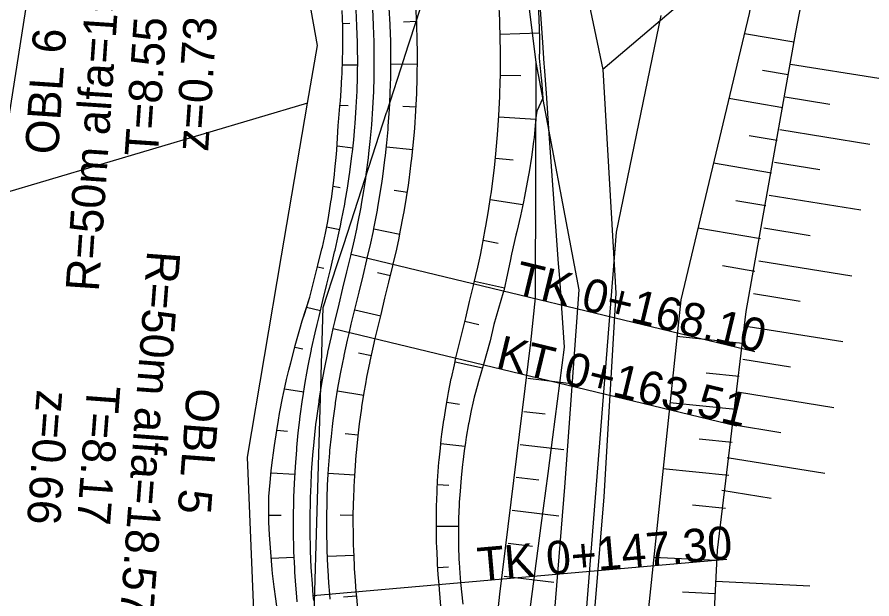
# Model space of a CAD drawing. Extents: x -583721 to -583071, y -1166145 to -1165065.
# Drawn here: x -583433.1 to -583381.7, y -1165506 to -1165470.9 of the extents above; entities that cross this region are included whole.
import ezdxf

# ---------------------------------------------------------------- set-up
doc = ezdxf.new("R2010")
doc.units = 0
for name, color, linetype in [('01_DOPRAVA', 7, 'Continuous'), ('03_PC_POPIS_NAVRH', 7, 'Continuous'), ('13', 7, 'Continuous'), ('14', 7, 'Continuous'), ('21', 7, 'Continuous'), ('_Rozpiska', 7, 'Continuous'), ('Kabel_navrh', 7, 'Continuous'), ('KOTY', 7, 'Continuous'), ('North Arrow', 7, 'Continuous'), ('Popis PP', 7, 'Continuous'), ('Rámy', 7, 'Continuous'), ('TISK', 7, 'Continuous')]:
    doc.layers.add(name, color=color, linetype=linetype)

msp = doc.modelspace()

# ---------------------------------------------------------------- linework, layer by layer
at = {"layer": '01_DOPRAVA'}
msp.add_line((-583415.62, -1165476.12), (-583516.013, -1165505.958), dxfattribs=at)
for points in [[(-583415.62, -1165476.12), (-583415.02, -1165472.65), (-583420.22, -1165443.6), (-583448.97, -1165365.39), (-583458.92, -1165347.2), (-583477.78, -1165313.78)], [(-583394.35, -1165470.85), (-583397.05, -1165483.9), (-583399.8, -1165518.65), (-583400, -1165542.33), (-583402.51, -1165559.81), (-583402.19, -1165563.54), (-583409.42, -1165564.02), (-583405.3, -1165586.77), (-583405.42, -1165638.41)], [(-583421.75, -1165552.72), (-583418.41, -1165517.42), (-583419.25, -1165497.44), (-583417.19, -1165485.32), (-583415.62, -1165476.12)]]:
    msp.add_lwpolyline(points, dxfattribs=at)
at = {"layer": '03_PC_POPIS_NAVRH'}
for points in [[(-583461.59, -1165302.25), (-583452.7, -1165330.11), (-583439.53, -1165361.89), (-583424.49, -1165398.09), (-583411.01, -1165432.01), (-583399.44, -1165466.53), (-583397.85, -1165474.11)], [(-583464.75, -1165303.13), (-583454.71, -1165331.15), (-583441.76, -1165362.61), (-583427, -1165399.08), (-583414.01, -1165432.94), (-583402.68, -1165467.21), (-583401.88, -1165473.68), (-583399.3, -1165487.37), (-583400.15, -1165499.25), (-583403.33, -1165538.26), (-583407.25, -1165561.02), (-583404.58, -1165574.64), (-583401.09, -1165602.76), (-583401.09, -1165613.37), (-583400.94, -1165621.86)], [(-583397.85, -1165474.11), (-583397.06, -1165487.57), (-583397.79, -1165499.84), (-583401.04, -1165539.21), (-583404.66, -1165561.5), (-583402.08, -1165573.97), (-583398.96, -1165602.08), (-583398.51, -1165613.27), (-583398.57, -1165622.21), (-583397.66, -1165628.38), (-583396.16, -1165631.68), (-583394.63, -1165634.22), (-583391.58, -1165635.84)]]:
    msp.add_lwpolyline(points, dxfattribs=at)
at = {"layer": '13'}
msp.add_lwpolyline([(-583416.289, -1165543.841), (-583416.022, -1165534.608), (-583415.796, -1165526.827), (-583415.773, -1165526.042), (-583415.472, -1165515.657), (-583415.378, -1165512.4), (-583415.341, -1165511.129), (-583415.238, -1165507.583), (-583415.019, -1165500.002), (-583414.683, -1165488.44), (-583413.859, -1165485.904), (-583413.741, -1165485.542), (-583413.723, -1165485.486), (-583413.45, -1165484.646), (-583410.865, -1165476.699), (-583410.858, -1165476.678), (-583409.783, -1165473.372), (-583409.781, -1165473.366), (-583407.515, -1165466.397)], dxfattribs=at)
at = {"layer": '14'}
for p, q in [((-583413.087, -1165471.34), (-583413.515, -1165471.359)), ((-583409.859, -1165471.234), (-583409.06, -1165471.199)), ((-583404.031, -1165471.963), (-583401.672, -1165471.901)), ((-583413.528, -1165473.815), (-583412.612, -1165473.82)), ((-583410.611, -1165473.768), (-583409.011, -1165473.776)), ((-583402.794, -1165474.483), (-583404.017, -1165474.463)), ((-583413.182, -1165476.291), (-583413.674, -1165476.262)), ((-583409.884, -1165476.31), (-583409.086, -1165476.353)), ((-583404.113, -1165476.961), (-583401.887, -1165477.095)), ((-583413.847, -1165478.706), (-583412.897, -1165478.81)), ((-583410.881, -1165478.759), (-583409.289, -1165478.924)), ((-583403.257, -1165479.563), (-583404.317, -1165479.452)), ((-583413.661, -1165481.218), (-583414.092, -1165481.149)), ((-583410.408, -1165481.359), (-583409.618, -1165481.481)), ((-583404.629, -1165481.933), (-583402.658, -1165482.225)), ((-583414.477, -1165483.579), (-583413.691, -1165483.744)), ((-583411.638, -1165483.699), (-583410.069, -1165484.017)), ((-583404.144, -1165484.571), (-583405.05, -1165484.397)), ((-583414.644, -1165486.087), (-583415.029, -1165485.996)), ((-583411.413, -1165486.319), (-583410.634, -1165486.502)), ((-583405.574, -1165486.841), (-583403.772, -1165487.251)), ((-583415.68, -1165488.413), (-583414.845, -1165488.609)), ((-583412.778, -1165488.567), (-583411.222, -1165488.938)), ((-583405.307, -1165489.477), (-583406.159, -1165489.272)), ((-583415.903, -1165490.943), (-583416.4, -1165490.841)), ((-583412.568, -1165491.167), (-583411.785, -1165491.334)), ((-583406.744, -1165491.702), (-583405.1, -1165492.068)), ((-583417.005, -1165493.324), (-583415.852, -1165493.505)), ((-583413.82, -1165493.456), (-583412.241, -1165493.716)), ((-583406.486, -1165494.283), (-583407.244, -1165494.151)), ((-583416.831, -1165495.913), (-583417.482, -1165495.843)), ((-583413.368, -1165496.022), (-583412.573, -1165496.111)), ((-583407.599, -1165496.626), (-583406.156, -1165496.789)), ((-583417.82, -1165498.392), (-583416.386, -1165498.474)), ((-583414.38, -1165498.422), (-583412.783, -1165498.52)), ((-583407.116, -1165499.154), (-583407.808, -1165499.116)), ((-583417.217, -1165500.966), (-583417.965, -1165500.96)), ((-583413.667, -1165500.928), (-583412.867, -1165500.936)), ((-583407.87, -1165501.615), (-583406.537, -1165501.609)), ((-583414.428, -1165503.42), (-583412.829, -1165503.355)), ((-583417.813, -1165503.527), (-583416.427, -1165503.472)), ((-583407.135, -1165504.076), (-583407.784, -1165504.113)), ((-583413.467, -1165505.853), (-583412.669, -1165505.792))]:
    msp.add_line(p, q, dxfattribs=at)
at = {"layer": '21'}
for points in [[(-583401.753, -1165469.827), (-583401.694, -1165471.025), (-583401.693, -1165471.072), (-583401.664, -1165472.224), (-583401.66, -1165472.918), (-583401.673, -1165473.423), (-583401.559, -1165474.624), (-583401.546, -1165474.767), (-583401.463, -1165475.83), (-583401.823, -1165476.606), (-583401.879, -1165477.011), (-583401.99, -1165478.203), (-583402.02, -1165478.439), (-583402.152, -1165479.388), (-583402.289, -1165480.262), (-583402.342, -1165480.569), (-583402.559, -1165481.744), (-583402.625, -1165482.071), (-583402.804, -1165482.912), (-583403.025, -1165483.864), (-583403.077, -1165484.073), (-583403.354, -1165485.231), (-583403.434, -1165485.65), (-583403.585, -1165486.397), (-583403.814, -1165487.441), (-583403.84, -1165487.538), (-583404.402, -1165489.46), (-583404.633, -1165490.433), (-583405.041, -1165491.872), (-583405.161, -1165492.267), (-583405.377, -1165493.027), (-583405.384, -1165493.052), (-583405.591, -1165493.843), (-583405.677, -1165494.193), (-583405.781, -1165494.639), (-583405.925, -1165495.373), (-583405.938, -1165495.442), (-583406.075, -1165496.25), (-583406.123, -1165496.562), (-583406.195, -1165497.06), (-583406.284, -1165497.759), (-583406.297, -1165497.873), (-583406.382, -1165498.689), (-583406.406, -1165498.961), (-583406.448, -1165499.507), (-583406.489, -1165500.166), (-583406.497, -1165500.326), (-583406.529, -1165501.147), (-583406.534, -1165501.375), (-583406.542, -1165501.968), (-583406.541, -1165502.585), (-583406.538, -1165502.79), (-583406.511, -1165503.611), (-583406.502, -1165503.795), (-583406.463, -1165504.432), (-583406.42, -1165505.003), (-583406.285, -1165506.299)], [(-583414.257, -1165505.995), (-583414.284, -1165505.693), (-583414.339, -1165505.012), (-583414.389, -1165504.253), (-583414.401, -1165504.034), (-583414.444, -1165503.055), (-583414.451, -1165502.811), (-583414.467, -1165502.075), (-583414.471, -1165501.368), (-583414.47, -1165501.095), (-583414.454, -1165500.115), (-583414.449, -1165499.925), (-583414.418, -1165499.136), (-583414.383, -1165498.483), (-583414.363, -1165498.158), (-583414.288, -1165497.18), (-583414.276, -1165497.043), (-583414.194, -1165496.205), (-583414.126, -1165495.607), (-583414.08, -1165495.232), (-583413.946, -1165494.261), (-583413.934, -1165494.177), (-583413.794, -1165493.293), (-583413.7, -1165492.753), (-583413.622, -1165492.328), (-583413.43, -1165491.367), (-583413.424, -1165491.336), (-583413.22, -1165490.41), (-583413.106, -1165489.928), (-583412.99, -1165489.447), (-583412.756, -1165488.475), (-583412.521, -1165487.503), (-583412.287, -1165486.53), (-583412.053, -1165485.558), (-583412.029, -1165485.46), (-583411.822, -1165484.567), (-583411.684, -1165483.928), (-583411.611, -1165483.569), (-583411.42, -1165482.567), (-583411.387, -1165482.385), (-583411.248, -1165481.562), (-583411.137, -1165480.835), (-583411.097, -1165480.553), (-583410.967, -1165479.541), (-583410.936, -1165479.277), (-583410.856, -1165478.527), (-583410.782, -1165477.714), (-583410.766, -1165477.511), (-583410.696, -1165476.494), (-583410.677, -1165476.147), (-583410.646, -1165475.475), (-583410.619, -1165474.577), (-583410.617, -1165474.455), (-583410.608, -1165473.435), (-583410.611, -1165473.006), (-583410.62, -1165472.416), (-583410.65, -1165471.436), (-583410.652, -1165471.396), (-583410.704, -1165470.377)], [(-583412.576, -1165506.851), (-583412.664, -1165505.855), (-583412.69, -1165505.553), (-583412.743, -1165504.894), (-583412.791, -1165504.161), (-583412.803, -1165503.948), (-583412.845, -1165503.001), (-583412.852, -1165502.766), (-583412.867, -1165502.054), (-583412.871, -1165501.369), (-583412.87, -1165501.106), (-583412.855, -1165500.158), (-583412.849, -1165499.973), (-583412.82, -1165499.21), (-583412.786, -1165498.578), (-583412.766, -1165498.264), (-583412.694, -1165497.319), (-583412.682, -1165497.186), (-583412.603, -1165496.375), (-583412.537, -1165495.797), (-583412.493, -1165495.434), (-583412.364, -1165494.494), (-583412.351, -1165494.413), (-583412.216, -1165493.558), (-583412.125, -1165493.035), (-583412.049, -1165492.625), (-583411.864, -1165491.695), (-583411.858, -1165491.665), (-583411.661, -1165490.769), (-583411.551, -1165490.303), (-583411.435, -1165489.822), (-583411.2, -1165488.85), (-583410.966, -1165487.878), (-583410.732, -1165486.906), (-583410.497, -1165485.933), (-583410.474, -1165485.835), (-583410.26, -1165484.914), (-583410.118, -1165484.255), (-583410.042, -1165483.885), (-583409.845, -1165482.851), (-583409.812, -1165482.664), (-583409.668, -1165481.814), (-583409.554, -1165481.065), (-583409.513, -1165480.774), (-583409.378, -1165479.731), (-583409.346, -1165479.458), (-583409.264, -1165478.685), (-583409.188, -1165477.846), (-583409.171, -1165477.637), (-583409.099, -1165476.587), (-583409.079, -1165476.229), (-583409.047, -1165475.537), (-583409.02, -1165474.61), (-583409.017, -1165474.485), (-583409.008, -1165473.433), (-583409.011, -1165472.991), (-583409.02, -1165472.381), (-583409.052, -1165471.371), (-583409.053, -1165471.33), (-583409.107, -1165470.279)], [(-583407.595, -1165506.414), (-583407.683, -1165505.418), (-583407.709, -1165505.116), (-583407.757, -1165504.527), (-583407.8, -1165503.871), (-583407.81, -1165503.681), (-583407.847, -1165502.834), (-583407.854, -1165502.623), (-583407.867, -1165501.986), (-583407.871, -1165501.374), (-583407.87, -1165501.138), (-583407.856, -1165500.29), (-583407.852, -1165500.125), (-583407.825, -1165499.443), (-583407.795, -1165498.877), (-583407.777, -1165498.596), (-583407.713, -1165497.751), (-583407.702, -1165497.632), (-583407.631, -1165496.907), (-583407.573, -1165496.389), (-583407.532, -1165496.064), (-583407.417, -1165495.224), (-583407.406, -1165495.152), (-583407.285, -1165494.387), (-583407.204, -1165493.919), (-583407.136, -1165493.552), (-583406.971, -1165492.72), (-583406.965, -1165492.693), (-583406.788, -1165491.892), (-583406.69, -1165491.475), (-583406.574, -1165490.994), (-583406.34, -1165490.022), (-583406.105, -1165489.05), (-583405.871, -1165488.077), (-583405.637, -1165487.105), (-583405.613, -1165487.007), (-583405.379, -1165485.998), (-583405.224, -1165485.276), (-583405.141, -1165484.871), (-583404.925, -1165483.74), (-583404.888, -1165483.535), (-583404.731, -1165482.604), (-583404.606, -1165481.783), (-583404.561, -1165481.465), (-583404.413, -1165480.322), (-583404.378, -1165480.024), (-583404.288, -1165479.177), (-583404.205, -1165478.258), (-583404.186, -1165478.03), (-583404.107, -1165476.88), (-583404.085, -1165476.488), (-583404.051, -1165475.73), (-583404.021, -1165474.715), (-583404.018, -1165474.578), (-583404.008, -1165473.426), (-583404.011, -1165472.941), (-583404.021, -1165472.274), (-583404.056, -1165471.168), (-583404.058, -1165471.123), (-583404.117, -1165469.973)], [(-583417.499, -1165506.279), (-583417.539, -1165505.978), (-583417.634, -1165505.255), (-583417.727, -1165504.447), (-583417.751, -1165504.213), (-583417.845, -1165503.169), (-583417.865, -1165502.909), (-583417.917, -1165502.122), (-583417.954, -1165501.365), (-583417.965, -1165501.073), (-583417.964, -1165500.022), (-583417.949, -1165499.818), (-583417.878, -1165498.975), (-583417.808, -1165498.277), (-583417.769, -1165497.931), (-583417.638, -1165496.89), (-583417.617, -1165496.744), (-583417.483, -1165495.853), (-583417.377, -1165495.22), (-583417.306, -1165494.821), (-583417.107, -1165493.795), (-583417.088, -1165493.706), (-583416.884, -1165492.773), (-583416.75, -1165492.205), (-583416.64, -1165491.759), (-583416.376, -1165490.75), (-583416.368, -1165490.717), (-583416.092, -1165489.748), (-583415.94, -1165489.244), (-583415.792, -1165488.771), (-583415.493, -1165487.815), (-583415.246, -1165486.846), (-583414.998, -1165485.877), (-583414.758, -1165484.906), (-583414.734, -1165484.808), (-583414.549, -1165483.961), (-583414.434, -1165483.354), (-583414.373, -1165483.013), (-583414.219, -1165482.062), (-583414.194, -1165481.889), (-583414.086, -1165481.108), (-583414.003, -1165480.419), (-583413.974, -1165480.151), (-583413.884, -1165479.194), (-583413.864, -1165478.944), (-583413.814, -1165478.235), (-583413.774, -1165477.466), (-583413.766, -1165477.275), (-583413.679, -1165476.319), (-583413.651, -1165475.992), (-583413.603, -1165475.361), (-583413.554, -1165474.515), (-583413.549, -1165474.401), (-583413.515, -1165473.439), (-583413.507, -1165473.035), (-583413.502, -1165472.477), (-583413.509, -1165471.552), (-583413.51, -1165471.514), (-583413.539, -1165470.552)], [(-583417.1, -1165509.255), (-583417.539, -1165505.978), (-583417.634, -1165505.255), (-583417.727, -1165504.447), (-583417.751, -1165504.213), (-583417.845, -1165503.169), (-583417.865, -1165502.909), (-583417.917, -1165502.122), (-583417.954, -1165501.365), (-583417.965, -1165501.073), (-583417.964, -1165500.022), (-583417.949, -1165499.818), (-583417.878, -1165498.975), (-583417.808, -1165498.277), (-583417.769, -1165497.931), (-583417.638, -1165496.89), (-583417.617, -1165496.744), (-583417.483, -1165495.853), (-583417.377, -1165495.22), (-583417.306, -1165494.821), (-583417.107, -1165493.795), (-583417.088, -1165493.706), (-583416.884, -1165492.773), (-583416.75, -1165492.205), (-583416.64, -1165491.759), (-583416.376, -1165490.75), (-583416.368, -1165490.717), (-583416.092, -1165489.748), (-583415.94, -1165489.244), (-583415.493, -1165487.815), (-583414.998, -1165485.877), (-583414.758, -1165484.906), (-583414.734, -1165484.808), (-583414.549, -1165483.961), (-583414.434, -1165483.354), (-583414.373, -1165483.013), (-583414.219, -1165482.062), (-583414.194, -1165481.889), (-583414.086, -1165481.108), (-583414.003, -1165480.419), (-583413.974, -1165480.151), (-583413.884, -1165479.194), (-583413.864, -1165478.944), (-583413.814, -1165478.235), (-583413.774, -1165477.466), (-583413.766, -1165477.275), (-583413.679, -1165476.319), (-583413.651, -1165475.992), (-583413.603, -1165475.361), (-583413.554, -1165474.515), (-583413.549, -1165474.401), (-583413.515, -1165473.439), (-583413.507, -1165473.035), (-583413.502, -1165472.477), (-583413.509, -1165471.552), (-583413.51, -1165471.514), (-583413.539, -1165470.552)], [(-583416.25, -1165506.169), (-583416.276, -1165505.868), (-583416.333, -1165505.159), (-583416.385, -1165504.369), (-583416.398, -1165504.141), (-583416.443, -1165503.122), (-583416.45, -1165502.868), (-583416.467, -1165502.102), (-583416.471, -1165501.366), (-583416.47, -1165501.082), (-583416.453, -1165500.062), (-583416.448, -1165499.864), (-583416.416, -1165499.043), (-583416.38, -1165498.363), (-583416.358, -1165498.025), (-583416.281, -1165497.008), (-583416.268, -1165496.865), (-583416.182, -1165495.992), (-583416.112, -1165495.371), (-583416.064, -1165494.979), (-583415.925, -1165493.969), (-583415.912, -1165493.882), (-583415.766, -1165492.961), (-583415.668, -1165492.399), (-583415.587, -1165491.957), (-583415.388, -1165490.957), (-583415.381, -1165490.924), (-583415.169, -1165489.961), (-583415.05, -1165489.459), (-583414.935, -1165488.978), (-583414.7, -1165488.006), (-583414.466, -1165487.034), (-583414.231, -1165486.062), (-583413.997, -1165485.09), (-583413.973, -1165484.991), (-583413.774, -1165484.133), (-583413.642, -1165483.519), (-583413.572, -1165483.174), (-583413.388, -1165482.212), (-583413.357, -1165482.037), (-583413.223, -1165481.246), (-583413.117, -1165480.547), (-583413.078, -1165480.276), (-583412.953, -1165479.305), (-583412.923, -1165479.051), (-583412.846, -1165478.33), (-583412.775, -1165477.549), (-583412.76, -1165477.354), (-583412.692, -1165476.377), (-583412.674, -1165476.043), (-583412.645, -1165475.398), (-583412.619, -1165474.535), (-583412.617, -1165474.418), (-583412.608, -1165473.438), (-583412.611, -1165473.026), (-583412.619, -1165472.458), (-583412.649, -1165471.517), (-583412.65, -1165471.479), (-583412.701, -1165470.5)]]:
    msp.add_lwpolyline(points, dxfattribs=at)
at = {"layer": '_Rozpiska'}
for points in [[(-583386.35, -1165472.46), (-583389.33, -1165471.95)], [(-583386.56, -1165473.77), (-583381.24, -1165474.63)], [(-583386.69, -1165474.43), (-583388.24, -1165474.17)], [(-583387.02, -1165476.4), (-583390.26, -1165475.85)], [(-583386.88, -1165475.75), (-583384.19, -1165476.18)], [(-583387.36, -1165478.37), (-583389.04, -1165478.09)], [(-583387.19, -1165477.72), (-583381.78, -1165478.59)], [(-583387.51, -1165479.69), (-583384.78, -1165480.13)], [(-583387.69, -1165480.35), (-583391.19, -1165479.75)], [(-583387.83, -1165481.67), (-583382.32, -1165482.56)], [(-583388.03, -1165482.32), (-583389.84, -1165482.01)], [(-583388.36, -1165484.29), (-583392.13, -1165483.65)], [(-583388.15, -1165483.64), (-583385.37, -1165484.09)], [(-583388.46, -1165485.62), (-583382.86, -1165486.52)], [(-583388.7, -1165486.26), (-583390.65, -1165485.93)], [(-583388.78, -1165487.59), (-583385.96, -1165488.05)], [(-583389.1, -1165489.57), (-583383.4, -1165490.48)], [(-583389.44, -1165490.6), (-583393.39, -1165490.19)], [(-583402.13, -1165490.72), (-583400.94, -1165490.86)], [(-583389.42, -1165491.54), (-583386.55, -1165492)], [(-583389.65, -1165492.59), (-583391.62, -1165492.39)], [(-583402.36, -1165492.7), (-583399.91, -1165493)], [(-583389.74, -1165493.52), (-583383.94, -1165494.45)], [(-583389.85, -1165494.58), (-583393.81, -1165494.17)], [(-583402.6, -1165494.69), (-583401.32, -1165494.84)], [(-583390.05, -1165495.49), (-583387.13, -1165495.96)], [(-583402.83, -1165496.68), (-583400.2, -1165496.99)], [(-583390.06, -1165496.57), (-583392.04, -1165496.37)], [(-583390.37, -1165497.47), (-583384.49, -1165498.41)], [(-583390.26, -1165498.56), (-583394.23, -1165498.15)], [(-583403.07, -1165498.66), (-583401.71, -1165498.82)], [(-583390.69, -1165499.44), (-583387.72, -1165499.92)], [(-583403.31, -1165500.65), (-583400.49, -1165500.98)], [(-583390.47, -1165500.55), (-583392.45, -1165500.34)], [(-583403.54, -1165502.63), (-583402.09, -1165502.81)], [(-583391, -1165503.68), (-583394.79, -1165503.49)], [(-583403.78, -1165504.62), (-583400.79, -1165504.98)], [(-583391.04, -1165504.91), (-583385.38, -1165505.2)], [(-583391.1, -1165505.68), (-583393.05, -1165505.58)]]:
    msp.add_lwpolyline(points, dxfattribs=at)
at = {"layer": 'Kabel_navrh'}
for points in [[(-583385.69, -1165452.31), (-583390.55, -1165467.88), (-583397.85, -1165474.11)], [(-583401.88, -1165473.68), (-583401.92, -1165487.86), (-583402.21, -1165490.54), (-583404.08, -1165505.7), (-583406.44, -1165527.95), (-583408.58, -1165548.59), (-583408.74, -1165560.73), (-583406.71, -1165575), (-583403.13, -1165607.61), (-583402.39, -1165613.68), (-583402.34, -1165622.12), (-583399.97, -1165635.46)]]:
    msp.add_lwpolyline(points, dxfattribs=at)
at = {"layer": 'KOTY'}
msp.add_lwpolyline([(-583415.254, -1165506.082), (-583415.28, -1165505.78), (-583415.336, -1165505.085), (-583415.387, -1165504.311), (-583415.4, -1165504.087), (-583415.443, -1165503.088), (-583415.451, -1165502.84), (-583415.467, -1165502.089), (-583415.471, -1165501.367), (-583415.47, -1165501.089), (-583415.454, -1165500.089), (-583415.448, -1165499.894), (-583415.417, -1165499.09), (-583415.382, -1165498.423), (-583415.361, -1165498.091), (-583415.284, -1165497.094), (-583415.272, -1165496.954), (-583415.188, -1165496.099), (-583415.119, -1165495.489), (-583415.072, -1165495.106), (-583414.936, -1165494.115), (-583414.923, -1165494.029), (-583414.78, -1165493.127), (-583414.684, -1165492.576), (-583414.604, -1165492.143), (-583414.409, -1165491.162), (-583414.402, -1165491.13), (-583414.194, -1165490.185), (-583414.078, -1165489.693), (-583413.962, -1165489.213), (-583413.728, -1165488.24), (-583413.494, -1165487.268), (-583413.259, -1165486.296), (-583413.025, -1165485.324), (-583413.001, -1165485.226), (-583412.798, -1165484.35), (-583412.663, -1165483.723), (-583412.591, -1165483.372), (-583412.404, -1165482.389), (-583412.372, -1165482.211), (-583412.236, -1165481.404), (-583412.127, -1165480.691), (-583412.088, -1165480.415), (-583411.96, -1165479.423), (-583411.929, -1165479.164), (-583411.851, -1165478.429), (-583411.779, -1165477.631), (-583411.763, -1165477.433), (-583411.694, -1165476.435), (-583411.675, -1165476.095), (-583411.645, -1165475.436), (-583411.619, -1165474.556), (-583411.617, -1165474.437), (-583411.608, -1165473.437), (-583411.611, -1165473.016), (-583411.62, -1165472.437), (-583411.649, -1165471.477), (-583411.651, -1165471.437), (-583411.702, -1165470.439)], dxfattribs=at)
at = {"layer": 'North Arrow'}
msp.add_lwpolyline([(-583406.29, -1165537.631), (-583405.45, -1165531.231), (-583402.899, -1165511.794), (-583401.556, -1165501.557), (-583401.145, -1165498.427), (-583400.859, -1165496.251), (-583400.148, -1165490.833), (-583400.317, -1165488.478), (-583400.383, -1165487.572), (-583400.447, -1165486.676), (-583400.511, -1165485.783), (-583400.992, -1165479.096), (-583401.073, -1165477.96), (-583401.248, -1165475.533), (-583401.362, -1165473.946), (-583401.377, -1165473.734), (-583401.468, -1165472.472), (-583401.631, -1165470.205), (-583402.096, -1165467.088), (-583402.861, -1165461.972), (-583403.655, -1165456.655), (-583403.873, -1165455.197)], dxfattribs=at)
at = {"layer": 'Popis PP'}
msp.add_lwpolyline([(-583453.882, -1165797.966), (-583451.761, -1165745.072), (-583447.631, -1165643.262), (-583446.859, -1165623.987), (-583445.813, -1165599.542), (-583444.662, -1165577.371), (-583442.034, -1165542.78), (-583439.667, -1165520.038), (-583436.68, -1165496.549), (-583431.494, -1165463.535), (-583426.631, -1165437.638), (-583422.051, -1165416.223), (-583417.441, -1165396.545), (-583410.087, -1165367.405), (-583389.989, -1165290.805), (-583376.799, -1165240.446), (-583367.037, -1165203.237), (-583351.367, -1165143.48), (-583345.203, -1165119.977)], dxfattribs=at)
at = {"layer": 'Rámy'}
for points in [[(-583381.01, -1165445.884), (-583385.4, -1165467.45), (-583386.25, -1165471.86), (-583389.24, -1165488.68)], [(-583385.69, -1165452.31), (-583389.03, -1165470.72), (-583393.16, -1165487.97), (-583398.62, -1165539.99), (-583394.89, -1165613.24), (-583393.56, -1165631.64)], [(-583389.24, -1165488.68), (-583390.97, -1165503.06), (-583392.87, -1165541.4), (-583390.29, -1165566.12)]]:
    msp.add_lwpolyline(points, dxfattribs=at)
at = {"layer": 'TISK'}
for points in [[(-583413.001, -1165485.226), (-583388.698, -1165491.086)], [(-583414.078, -1165489.693), (-583389.775, -1165495.553)], [(-583415.28, -1165505.78), (-583390.376, -1165503.597)]]:
    msp.add_lwpolyline(points, dxfattribs=at)

# ---------------------------------------------------------------- texts
for s, rotation, p in [('R=50m alfa=19.41%%d', 86.1499, (-583428.197, -1165487.506)), ('  T=8.55', 86.1499, (-583424.744, -1165480.868)), ('   z=0.73', 86.1499, (-583421.766, -1165481.298)), ('OBL 6', 86.1499, (-583430.649, -1165479.26)), ('R=50m alfa=18.57%%d', 265.7276, (-583425.274, -1165484.977)), ('TK 0+168.10', 346.4441, (-583403.28, -1165487.57)), ('KT 0+163.51', 346.4441, (-583404.357, -1165492.037)), ('   z=0.66', 265.7276, (-583431.751, -1165491.136)), ('  T=8.17', 265.7276, (-583428.776, -1165491.595)), ('OBL 5', 265.7276, (-583422.882, -1165493.237)), ('TK 0+147.30', 5.0111, (-583405.318, -1165504.907))]:
    msp.add_text(s, height=2, rotation=rotation, dxfattribs=at).set_placement(p)

doc.saveas('drawing.dxf')
